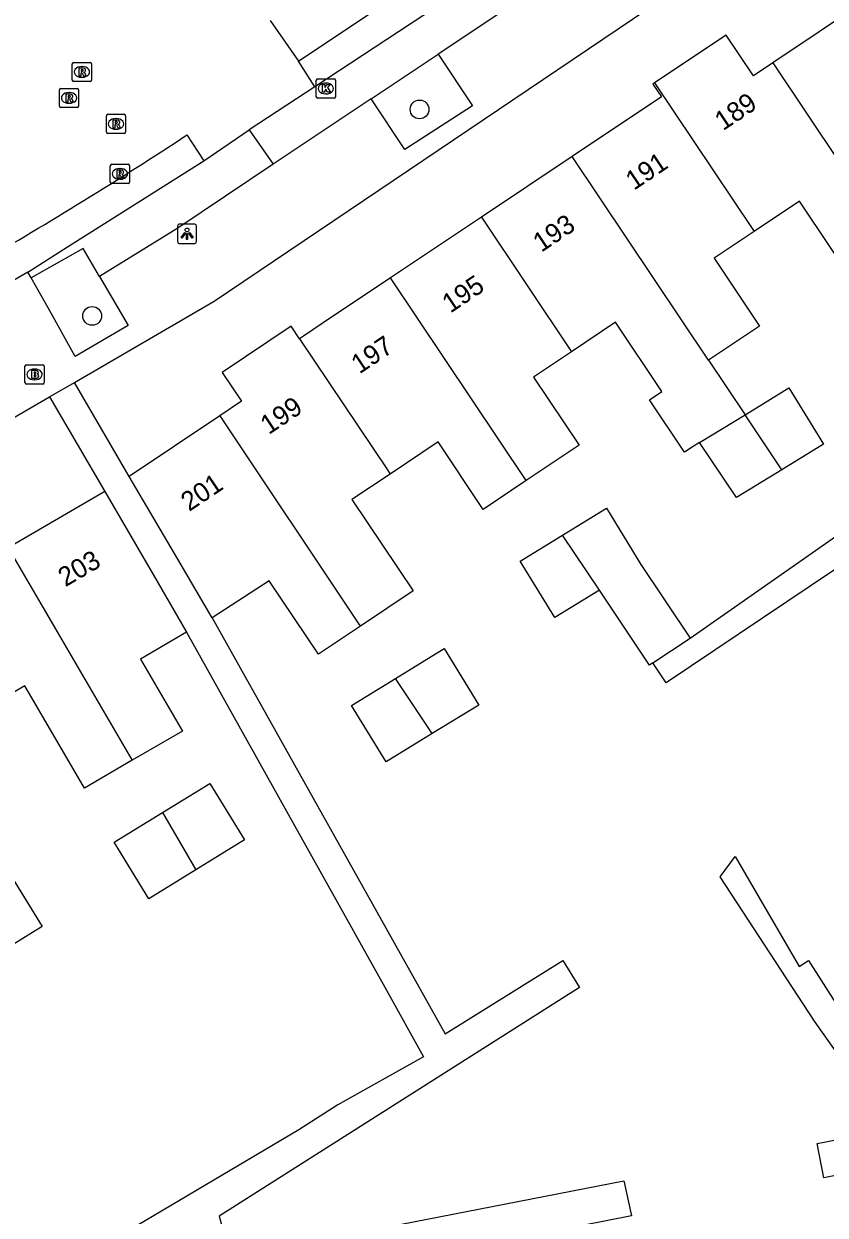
# Model space of a CAD drawing. Extents: x 158352 to 159489, y 383828 to 384597.
# Drawn here: x 158744.7 to 158786.5, y 384106.4 to 384168.5 of the extents above; entities that cross this region are included whole.
import ezdxf

# ---------------------------------------------------------------- set-up
doc = ezdxf.new("R2010")
doc.units = 0
for name, color, linetype in [('IMGEO_Boom', 7, 'Continuous'), ('IMGEO_Brandkraan', 7, 'Continuous'), ('IMGEO_Kolk', 7, 'Continuous'), ('IMGEO_Lichtpunt', 7, 'Continuous'), ('IMGEO_Pand', 7, 'Continuous'), ('IMGEO_Pand_nummerreeks', 7, 'Continuous'), ('IMGEO_Parkeervlak_open', 7, 'Continuous'), ('IMGEO_Rijbaan_lokaal_gesloten', 7, 'Continuous'), ('IMGEO_Rijbaan_lokaal_open', 7, 'Continuous'), ('IMGEO_Rioolput', 7, 'Continuous'), ('IMGEO_Voetpad_open', 7, 'Continuous')]:
    doc.layers.add(name, color=color, linetype=linetype)

msp = doc.modelspace()

# ---------------------------------------------------------------- linework, layer by layer
at = {"layer": 'IMGEO_Boom'}
for centre in [(158765.335, 384164.034), (158748.282, 384153.276)]:
    msp.add_circle(centre, 0.489, dxfattribs=at)
at = {"layer": 'IMGEO_Brandkraan'}
for p, q in [((158744.78, 384149.802), (158744.78, 384150.654)), ((158744.855, 384150.728), (158745.707, 384150.728)), ((158745.781, 384150.654), (158745.781, 384149.802)), ((158745.268, 384150.508), (158745.293, 384150.508)), ((158745.707, 384149.728), (158744.855, 384149.728)), ((158745.291, 384149.948), (158745.266, 384149.948))]:
    msp.add_line(p, q, dxfattribs=at)
for points in [[(158744.78, 384149.802), (158744.78, 384150.654)], [(158744.855, 384150.728), (158745.707, 384150.728)], [(158745.781, 384150.654), (158745.781, 384149.802)], [(158745.128, 384150.428), (158745.128, 384150.028), (158745.341, 384150.028)], [(158745.359, 384150.428), (158745.128, 384150.428)], [(158745.307, 384150.347), (158745.253, 384150.347), (158745.253, 384150.271)], [(158745.253, 384150.271), (158745.306, 384150.271)], [(158745.315, 384150.195), (158745.253, 384150.195), (158745.253, 384150.114)], [(158745.253, 384150.114), (158745.315, 384150.114)], [(158745.707, 384149.728), (158744.855, 384149.728)]]:
    msp.add_lwpolyline(points, dxfattribs=at)
for centre, radius, start, end in [((158744.857, 384150.652), 0.0765, 91.55205, 178.44795), ((158744.857, 384150.652), 0.0765, 91.55205, 178.44795), ((158745.705, 384150.652), 0.0765, 1.55205, 88.44795), ((158745.705, 384150.652), 0.0765, 1.55205, 88.44795), ((158745.308, 384150.309), 0.0379, 267.82845, 90.93552), ((158745.316, 384150.154), 0.0404, 269.87594, 90.50774), ((158745.347, 384150.279), 0.251, 268.66757, 293.53466), ((158745.363, 384150.283), 0.145, 59.4692, 91.53667), ((158745.388, 384150.33), 0.0922, 285.51372, 58.15012), ((158745.393, 384150.138), 0.105, 301.31148, 78.98903), ((158744.857, 384149.804), 0.0765, 181.55205, 268.44795), ((158744.857, 384149.804), 0.0765, 181.55205, 268.44795), ((158745.705, 384149.804), 0.0765, 271.55205, 358.44795), ((158745.705, 384149.804), 0.0765, 271.55205, 358.44795)]:
    msp.add_arc(centre, radius, start, end, dxfattribs=at)
for centre, major_axis, ratio, start_param, end_param in [((158745.267, 384150.228), (-0.387, 0.002), 0.722429, 4.712389, 7.853982), ((158745.292, 384150.228), (-0.39, 0.002), 0.717154, 1.570796, 4.712389)]:
    msp.add_ellipse(centre, major_axis=major_axis, ratio=ratio, start_param=start_param, end_param=end_param, dxfattribs=at)
at = {"layer": 'IMGEO_Kolk'}
for p, q in [((158759.954, 384164.699), (158759.954, 384165.551)), ((158760.029, 384165.625), (158760.881, 384165.625)), ((158760.955, 384165.551), (158760.955, 384164.699)), ((158760.442, 384165.405), (158760.467, 384165.405)), ((158760.881, 384164.625), (158760.029, 384164.625)), ((158760.465, 384164.845), (158760.44, 384164.845))]:
    msp.add_line(p, q, dxfattribs=at)
for points in [[(158759.954, 384164.699), (158759.954, 384165.551)], [(158760.029, 384165.625), (158760.881, 384165.625)], [(158760.955, 384165.551), (158760.955, 384164.699)], [(158760.275, 384165.325), (158760.398, 384165.325), (158760.398, 384165.174), (158760.528, 384165.325), (158760.692, 384165.325), (158760.546, 384165.174), (158760.699, 384164.925), (158760.547, 384164.925), (158760.462, 384165.089), (158760.398, 384165.022), (158760.398, 384164.925), (158760.275, 384164.925), (158760.275, 384165.325)], [(158760.881, 384164.625), (158760.029, 384164.625)]]:
    msp.add_lwpolyline(points, dxfattribs=at)
for centre, start, end in [((158760.031, 384165.549), 91.55205, 178.44795), ((158760.031, 384165.549), 91.55205, 178.44795), ((158760.879, 384165.549), 1.55205, 88.44795), ((158760.879, 384165.549), 1.55205, 88.44795), ((158760.031, 384164.701), 181.55205, 268.44795), ((158760.031, 384164.701), 181.55205, 268.44795), ((158760.879, 384164.701), 271.55205, 358.44795), ((158760.879, 384164.701), 271.55205, 358.44795)]:
    msp.add_arc(centre, 0.0765, start, end, dxfattribs=at)
for centre, major_axis, ratio, start_param, end_param in [((158760.441, 384165.125), (-0.387, 0.002), 0.722429, 4.712389, 7.853982), ((158760.466, 384165.125), (-0.39, 0.002), 0.717154, 1.570796, 4.712389)]:
    msp.add_ellipse(centre, major_axis=major_axis, ratio=ratio, start_param=start_param, end_param=end_param, dxfattribs=at)
at = {"layer": 'IMGEO_Lichtpunt'}
for p, q in [((158752.727, 384157.959), (158752.727, 384157.152)), ((158752.727, 384157.959), (158752.727, 384157.152)), ((158753.629, 384158.054), (158752.821, 384158.054)), ((158753.629, 384158.054), (158752.821, 384158.054)), ((158753.723, 384157.152), (158753.723, 384157.959)), ((158753.723, 384157.152), (158753.723, 384157.959)), ((158752.821, 384157.058), (158753.629, 384157.058)), ((158752.821, 384157.058), (158753.629, 384157.058))]:
    msp.add_line(p, q, dxfattribs=at)
for points in [[(158753.101, 384157.623), (158753.14, 384157.595), (158752.952, 384157.333), (158752.914, 384157.36), (158753.101, 384157.623)], [(158753.203, 384157.575), (158753.25, 384157.575), (158753.25, 384157.253), (158753.203, 384157.253), (158753.203, 384157.575)], [(158753.313, 384157.595), (158753.351, 384157.622), (158753.538, 384157.36), (158753.499, 384157.332), (158753.313, 384157.595)]]:
    msp.add_lwpolyline(points, dxfattribs=at)
msp.add_circle((158753.226, 384157.757), 0.0994, dxfattribs=at)
for centre, start, end in [((158752.821, 384157.959), 90, 180), ((158752.821, 384157.959), 90, 180), ((158753.629, 384157.959), 0, 90), ((158753.629, 384157.959), 0, 90), ((158752.821, 384157.152), 180, 270), ((158752.821, 384157.152), 180, 270), ((158753.629, 384157.152), 270, 0), ((158753.629, 384157.152), 270, 360)]:
    msp.add_arc(centre, 0.0946, start, end, dxfattribs=at)
at = {"layer": 'IMGEO_Pand'}
for points in [[(158788.571, 384169.689), (158783.739, 384166.456)], [(158783.739, 384166.456), (158782.733, 384165.783), (158781.31, 384167.91), (158777.582, 384165.415)], [(158783.739, 384166.456), (158790.756, 384155.965)], [(158777.582, 384165.415), (158777.49, 384165.354), (158777.931, 384164.695), (158773.289, 384161.59)], [(158777.582, 384165.415), (158782.694, 384157.773), (158782.763, 384157.67)], [(158773.289, 384161.59), (158768.555, 384158.422)], [(158780.395, 384150.966), (158773.289, 384161.59)], [(158790.756, 384155.965), (158788.992, 384154.785), (158788.389, 384154.381), (158785.129, 384159.253), (158782.763, 384157.67)], [(158768.555, 384158.422), (158763.821, 384155.256)], [(158768.555, 384158.422), (158773.25, 384151.404)], [(158782.763, 384157.67), (158780.686, 384156.281), (158783.052, 384152.744), (158780.395, 384150.966)], [(158763.821, 384155.256), (158760.269, 384152.879), (158759.288, 384152.223), (158759.088, 384152.089)], [(158770.887, 384144.694), (158763.821, 384155.256)], [(158759.088, 384152.089), (158758.65, 384152.744), (158755.051, 384150.336), (158756.059, 384148.83), (158754.924, 384148.07)], [(158779.923, 384146.675), (158779.584, 384146.467), (158779.142, 384146.171), (158777.313, 384148.904), (158777.963, 384149.339), (158775.551, 384152.943), (158773.25, 384151.404)], [(158759.088, 384152.089), (158763.663, 384145.25), (158763.803, 384145.041)], [(158773.25, 384151.404), (158771.279, 384150.085), (158773.649, 384146.543), (158770.887, 384144.694)], [(158780.395, 384150.966), (158782.292, 384148.129)], [(158782.292, 384148.129), (158784.574, 384149.53), (158786.378, 384146.591), (158784.211, 384145.261)], [(158754.924, 384148.07), (158750.204, 384144.913)], [(158754.924, 384148.07), (158762.181, 384137.223), (158762.253, 384137.116)], [(158779.923, 384146.675), (158782.292, 384148.129)], [(158784.211, 384145.261), (158782.292, 384148.129)], [(158770.887, 384144.694), (158768.652, 384143.199), (158766.302, 384146.712), (158763.803, 384145.041)], [(158784.211, 384145.261), (158781.84, 384143.809), (158779.923, 384146.675)], [(158754.537, 384137.547), (158752.739, 384140.604), (158750.204, 384144.913)], [(158763.803, 384145.041), (158761.815, 384143.711), (158764.999, 384138.953), (158762.253, 384137.116)], [(158748.936, 384144.128), (158743.915, 384141.203)], [(158748.936, 384144.128), (158751.452, 384139.808), (158753.204, 384136.8)], [(158772.785, 384141.858), (158775.066, 384143.258), (158776.87, 384140.319), (158779.428, 384136.495)], [(158774.703, 384138.989), (158772.377, 384137.561), (158770.574, 384140.5), (158772.785, 384141.858)], [(158774.703, 384138.989), (158772.785, 384141.858)], [(158743.915, 384141.203), (158750.233, 384130.355), (158750.367, 384130.126)], [(158762.253, 384137.116), (158760.068, 384135.654), (158757.506, 384139.484), (158754.537, 384137.547)], [(158777.488, 384135.197), (158777.317, 384135.083), (158774.703, 384138.989)], [(158753.204, 384136.8), (158750.796, 384135.397), (158752.98, 384131.648), (158750.367, 384130.126)], [(158777.488, 384135.197), (158779.428, 384136.495)], [(158764.079, 384134.387), (158766.618, 384135.945), (158768.422, 384133.006), (158765.998, 384131.518)], [(158750.367, 384130.126), (158747.874, 384128.674), (158744.766, 384134.011), (158742.341, 384132.599)], [(158765.998, 384131.518), (158763.591, 384130.042), (158761.788, 384132.981), (158764.079, 384134.387)], [(158765.998, 384131.518), (158764.079, 384134.387)], [(158751.95, 384127.408), (158754.412, 384128.919), (158756.216, 384125.98), (158753.686, 384124.427)], [(158753.686, 384124.427), (158751.225, 384122.917), (158749.422, 384125.856), (158751.95, 384127.408)], [(158751.95, 384127.408), (158753.686, 384124.427)], [(158741.411, 384122.887), (158743.874, 384124.399), (158745.678, 384121.46), (158743.147, 384119.907)]]:
    msp.add_lwpolyline(points, dxfattribs=at)
at = {"layer": 'IMGEO_Parkeervlak_open'}
for points in [[(158762.82, 384164.587), (158766.3, 384166.915)], [(158756.455, 384162.969), (158757.707, 384161.186)], [(158748.663, 384155.332), (158747.814, 384156.79), (158745.105, 384155.259)]]:
    msp.add_lwpolyline(points, dxfattribs=at)
at = {"layer": 'IMGEO_Rijbaan_lokaal_gesloten'}
for points in [[(158759.023, 384166.554), (158779.647, 384180.327), (158780.635, 384178.907)], [(158780.514, 384178.796), (158759.872, 384165.217)], [(158744.935, 384155.56), (158746.999, 384156.883), (158754.1, 384161.357)], [(158744.935, 384155.56), (158742.681, 384154.246)]]:
    msp.add_lwpolyline(points, dxfattribs=at)
at = {"layer": 'IMGEO_Rijbaan_lokaal_open'}
for points in [[(158757.561, 384168.674), (158759.023, 384166.554)], [(158759.872, 384165.217), (158759.023, 384166.554)], [(158759.872, 384165.217), (158756.455, 384162.969)], [(158753.215, 384162.703), (158754.1, 384161.357)], [(158754.1, 384161.357), (158756.455, 384162.969)]]:
    msp.add_lwpolyline(points, dxfattribs=at)
msp.add_arc((158636.507, 384340.07), 212.32, 299.91064, 303.34507, dxfattribs=at)
at = {"layer": 'IMGEO_Rioolput'}
for p, q in [((158747.246, 384165.56), (158747.246, 384166.412)), ((158747.321, 384166.486), (158748.173, 384166.486)), ((158747.734, 384166.266), (158747.759, 384166.266)), ((158748.247, 384166.412), (158748.247, 384165.56)), ((158747.757, 384165.706), (158747.732, 384165.706)), ((158746.576, 384164.206), (158746.576, 384165.058)), ((158746.651, 384165.132), (158747.503, 384165.132)), ((158748.173, 384165.486), (158747.321, 384165.486)), ((158747.577, 384165.058), (158747.577, 384164.206)), ((158747.087, 384164.352), (158747.062, 384164.352)), ((158747.064, 384164.912), (158747.089, 384164.912)), ((158747.503, 384164.132), (158746.651, 384164.132)), ((158749.023, 384162.854), (158749.023, 384163.706)), ((158749.098, 384163.78), (158749.95, 384163.78)), ((158750.024, 384163.706), (158750.024, 384162.854)), ((158749.511, 384163.56), (158749.536, 384163.56)), ((158749.95, 384162.78), (158749.098, 384162.78)), ((158749.534, 384163), (158749.509, 384163)), ((158749.226, 384160.251), (158749.226, 384161.103)), ((158749.301, 384161.177), (158750.153, 384161.177)), ((158749.714, 384160.957), (158749.739, 384160.957)), ((158750.227, 384161.103), (158750.227, 384160.251)), ((158750.153, 384160.177), (158749.301, 384160.177)), ((158749.737, 384160.397), (158749.712, 384160.397))]:
    msp.add_line(p, q, dxfattribs=at)
for points in [[(158747.246, 384165.56), (158747.246, 384166.412)], [(158747.321, 384166.486), (158748.173, 384166.486)], [(158747.835, 384166.184), (158747.583, 384166.186), (158747.583, 384165.786)], [(158748.247, 384166.412), (158748.247, 384165.56)], [(158747.583, 384165.786), (158747.707, 384165.786), (158747.707, 384165.948), (158747.718, 384165.948)], [(158747.761, 384166.105), (158747.707, 384166.105), (158747.707, 384166.024)], [(158747.707, 384166.024), (158747.759, 384166.024)], [(158747.765, 384165.919), (158747.836, 384165.786), (158747.976, 384165.786), (158747.911, 384165.912)], [(158746.576, 384164.206), (158746.576, 384165.058)], [(158746.651, 384165.132), (158747.503, 384165.132)], [(158748.173, 384165.486), (158747.321, 384165.486)], [(158747.577, 384165.058), (158747.577, 384164.206)], [(158747.165, 384164.83), (158746.913, 384164.832), (158746.913, 384164.432)], [(158746.913, 384164.432), (158747.037, 384164.432), (158747.037, 384164.594), (158747.048, 384164.594)], [(158747.091, 384164.751), (158747.037, 384164.751), (158747.037, 384164.67)], [(158747.037, 384164.67), (158747.089, 384164.67)], [(158747.095, 384164.565), (158747.166, 384164.432), (158747.306, 384164.432), (158747.241, 384164.558)], [(158747.503, 384164.132), (158746.651, 384164.132)], [(158749.023, 384162.854), (158749.023, 384163.706)], [(158749.098, 384163.78), (158749.95, 384163.78)], [(158750.024, 384163.706), (158750.024, 384162.854)], [(158749.612, 384163.478), (158749.36, 384163.48), (158749.36, 384163.08)], [(158749.36, 384163.08), (158749.484, 384163.08), (158749.484, 384163.242), (158749.495, 384163.242)], [(158749.538, 384163.399), (158749.484, 384163.399), (158749.484, 384163.318)], [(158749.484, 384163.318), (158749.536, 384163.318)], [(158749.542, 384163.213), (158749.613, 384163.08), (158749.753, 384163.08), (158749.688, 384163.206)], [(158749.95, 384162.78), (158749.098, 384162.78)], [(158749.226, 384160.251), (158749.226, 384161.103)], [(158749.301, 384161.177), (158750.153, 384161.177)], [(158749.815, 384160.875), (158749.563, 384160.877), (158749.563, 384160.477)], [(158749.563, 384160.477), (158749.687, 384160.477), (158749.687, 384160.639), (158749.698, 384160.639)], [(158749.741, 384160.796), (158749.687, 384160.796), (158749.687, 384160.715)], [(158749.687, 384160.715), (158749.739, 384160.715)], [(158749.745, 384160.61), (158749.816, 384160.477), (158749.956, 384160.477), (158749.891, 384160.603)], [(158750.227, 384161.103), (158750.227, 384160.251)], [(158750.153, 384160.177), (158749.301, 384160.177)]]:
    msp.add_lwpolyline(points, dxfattribs=at)
for centre, radius, start, end in [((158747.323, 384166.41), 0.0765, 91.55205, 178.44795), ((158747.323, 384166.41), 0.0765, 91.55205, 178.44795), ((158747.834, 384166.074), 0.109, 350.36119, 89.41601), ((158748.171, 384166.41), 0.0765, 1.55205, 88.44795), ((158748.171, 384166.41), 0.0765, 1.55205, 88.44795), ((158747.323, 384165.562), 0.0765, 181.55205, 268.44795), ((158747.323, 384165.562), 0.0765, 181.55205, 268.44795), ((158747.717, 384165.895), 0.0533, 26.02933, 88.69889), ((158747.743, 384166.213), 0.19, 274.7715, 282.96867), ((158747.767, 384166.009), 0.0964, 77.00612, 93.18647), ((158747.781, 384166.066), 0.0378, 276.66336, 79.67722), ((158747.832, 384166.074), 0.112, 277.58423, 350.98172), ((158747.816, 384165.859), 0.108, 29.51342, 73.79051), ((158748.171, 384165.562), 0.0765, 271.55205, 358.44795), ((158748.171, 384165.562), 0.0765, 271.55205, 358.44795), ((158746.653, 384165.056), 0.0765, 91.55205, 178.44795), ((158746.653, 384165.056), 0.0765, 91.55205, 178.44795), ((158747.501, 384165.056), 0.0765, 1.55205, 88.44795), ((158747.501, 384165.056), 0.0765, 1.55205, 88.44795), ((158747.047, 384164.541), 0.0533, 26.02933, 88.69889), ((158747.073, 384164.859), 0.19, 274.7715, 282.96867), ((158747.097, 384164.655), 0.0964, 77.00612, 93.18647), ((158747.111, 384164.712), 0.0378, 276.66336, 79.67722), ((158747.164, 384164.72), 0.109, 350.36119, 89.41601), ((158747.162, 384164.72), 0.112, 277.58423, 350.98172), ((158747.146, 384164.505), 0.108, 29.51342, 73.79051), ((158746.653, 384164.208), 0.0765, 181.55205, 268.44795), ((158746.653, 384164.208), 0.0765, 181.55205, 268.44795), ((158747.501, 384164.208), 0.0765, 271.55205, 358.44795), ((158747.501, 384164.208), 0.0765, 271.55205, 358.44795), ((158749.1, 384163.704), 0.0765, 91.55205, 178.44795), ((158749.1, 384163.704), 0.0765, 91.55205, 178.44795), ((158749.948, 384163.704), 0.0765, 1.55205, 88.44795), ((158749.948, 384163.704), 0.0765, 1.55205, 88.44795), ((158749.494, 384163.189), 0.0533, 26.02933, 88.69889), ((158749.52, 384163.507), 0.19, 274.7715, 282.96867), ((158749.544, 384163.303), 0.0964, 77.00612, 93.18647), ((158749.558, 384163.36), 0.0378, 276.66336, 79.67722), ((158749.611, 384163.368), 0.109, 350.36119, 89.41601), ((158749.609, 384163.368), 0.112, 277.58423, 350.98172), ((158749.593, 384163.153), 0.108, 29.51342, 73.79051), ((158749.1, 384162.856), 0.0765, 181.55205, 268.44795), ((158749.1, 384162.856), 0.0765, 181.55205, 268.44795), ((158749.948, 384162.856), 0.0765, 271.55205, 358.44795), ((158749.948, 384162.856), 0.0765, 271.55205, 358.44795), ((158749.303, 384161.101), 0.0765, 91.55205, 178.44795), ((158749.303, 384161.101), 0.0765, 91.55205, 178.44795), ((158749.697, 384160.586), 0.0533, 26.02933, 88.69889), ((158749.723, 384160.904), 0.19, 274.7715, 282.96867), ((158749.747, 384160.7), 0.0964, 77.00612, 93.18647), ((158749.761, 384160.757), 0.0378, 276.66336, 79.67722), ((158749.814, 384160.765), 0.109, 350.36119, 89.41601), ((158749.812, 384160.765), 0.112, 277.58423, 350.98172), ((158749.796, 384160.55), 0.108, 29.51342, 73.79051), ((158750.151, 384161.101), 0.0765, 1.55205, 88.44795), ((158750.151, 384161.101), 0.0765, 1.55205, 88.44795), ((158749.303, 384160.253), 0.0765, 181.55205, 268.44795), ((158749.303, 384160.253), 0.0765, 181.55205, 268.44795), ((158750.151, 384160.253), 0.0765, 271.55205, 358.44795), ((158750.151, 384160.253), 0.0765, 271.55205, 358.44795)]:
    msp.add_arc(centre, radius, start, end, dxfattribs=at)
for centre, major_axis, ratio, start_param, end_param in [((158747.733, 384165.986), (-0.387, 0.002), 0.722429, 4.712389, 7.853982), ((158747.758, 384165.986), (-0.39, 0.002), 0.717154, 1.570796, 4.712389), ((158747.063, 384164.632), (-0.387, 0.002), 0.722429, 4.712389, 7.853982), ((158747.088, 384164.632), (-0.39, 0.002), 0.717154, 1.570796, 4.712389), ((158749.51, 384163.28), (-0.387, 0.002), 0.722429, 4.712389, 7.853982), ((158749.535, 384163.28), (-0.39, 0.002), 0.717154, 1.570796, 4.712389), ((158749.713, 384160.677), (-0.387, 0.002), 0.722429, 4.712389, 7.853982), ((158749.738, 384160.677), (-0.39, 0.002), 0.717154, 1.570796, 4.712389)]:
    msp.add_ellipse(centre, major_axis=major_axis, ratio=ratio, start_param=start_param, end_param=end_param, dxfattribs=at)
at = {"layer": 'IMGEO_Voetpad_open'}
for points in [[(158778.824, 384175.261), (158766.3, 384166.915)], [(158747.356, 384149.809), (158754.637, 384154.044), (158777.222, 384169.281), (158785.32, 384174.656)], [(158766.3, 384166.915), (158768.085, 384164.229), (158764.575, 384161.944), (158762.82, 384164.587)], [(158762.82, 384164.587), (158757.707, 384161.186)], [(158757.707, 384161.186), (158752.738, 384157.847), (158748.663, 384155.332)], [(158745.105, 384155.259), (158744.935, 384155.56)], [(158748.663, 384155.332), (158750.151, 384152.773), (158747.404, 384151.165), (158745.988, 384153.697), (158745.105, 384155.259)], [(158746.068, 384149.06), (158747.356, 384149.809)], [(158750.204, 384144.913), (158747.356, 384149.809)], [(158696.667, 384120.326), (158746.068, 384149.06)], [(158746.068, 384149.06), (158748.936, 384144.128)], [(158779.428, 384136.495), (158796.192, 384148.218)], [(158794.5, 384145.112), (158778.188, 384134.155), (158777.488, 384135.197)], [(158754.537, 384137.547), (158766.668, 384115.877), (158772.792, 384119.688), (158773.666, 384118.284), (158754.906, 384106.382), (158755.484, 384104.227), (158775.984, 384108.212), (158776.375, 384106.398), (158766.085, 384104.362), (158769.377, 384087.719)], [(158753.204, 384136.8), (158763.607, 384118.148), (158765.544, 384114.675), (158761.079, 384112.184), (158759.047, 384110.871), (158749.715, 384105.347), (158745.966, 384103.699), (158746.706, 384102.014)], [(158818.168, 384105.423), (158796.617, 384101.391), (158791.026, 384109.296), (158786.396, 384108.38), (158786.05, 384110.169), (158789.881, 384110.914), (158785.908, 384116.531), (158780.99, 384124.051), (158781.781, 384125.11), (158785.11, 384119.38), (158785.601, 384119.692), (158787.121, 384117.303), (158796.472, 384103.825), (158798.597, 384103.4), (158814.313, 384106.219)]]:
    msp.add_lwpolyline(points, dxfattribs=at)

# ---------------------------------------------------------------- texts
at = {"layer": 'IMGEO_Pand_nummerreeks'}
for s, rotation, p in [('189', 33.78217, (158781.143, 384162.897)), ('191', 33.78217, (158776.504, 384159.795)), ('193', 33.78159, (158771.676, 384156.564)), ('195', 33.78217, (158766.942, 384153.397)), ('197', 33.78159, (158762.208, 384150.23)), ('199', 33.78159, (158757.474, 384147.063)), ('201', 33.77682, (158753.335, 384143.061)), ('203', 30.23656, (158746.887, 384139.138))]:
    msp.add_text(s, height=1, rotation=rotation, dxfattribs=at).set_placement(p)

doc.saveas('drawing.dxf')
